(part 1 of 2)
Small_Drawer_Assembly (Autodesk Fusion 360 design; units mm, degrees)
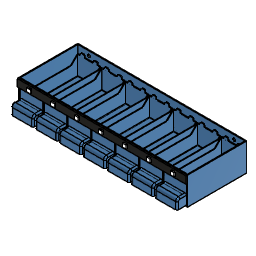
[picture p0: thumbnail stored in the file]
sketch "Sketch1" plane through (0, 0, 0) normal (0, 0, 1) x axis (1, 0, 0)
  line L1 (232.6, 0) -> (0, 0)
  line L2 (232.6, 81.6) -> (232.6, 0)
  line L3 (0, 81.6) -> (232.6, 81.6)
  line L4 (0, 0) -> (0, 81.6)
  line L5 (231.4, 80.4) -> (1.2, 80.4)
  line L6 (231.4, 1.2) -> (231.4, 80.4)
  line L7 (1.2, 1.2) -> (231.4, 1.2)
  line L8 (1.2, 80.4) -> (1.2, 1.2)
  line L9 (31.4, 78.4) -> (3.2, 78.4)
  line L10 (31.4, 3.2) -> (31.4, 78.4)
  line L11 (3.2, 3.2) -> (31.4, 3.2)
  line L12 (3.2, 78.4) -> (3.2, 3.2)
  line L13 (34.2, 80.4) -> (33.4, 80.4)
  line L14 (34.2, 1.2) -> (34.2, 80.4)
  line L15 (33.4, 1.2) -> (34.2, 1.2)
  line L16 (33.4, 80.4) -> (33.4, 1.2)
  line L17 (64.4, 78.4) -> (36.2, 78.4)
  line L18 (36.2, 78.4) -> (36.2, 3.2)
  line L19 (64.4, 3.2) -> (64.4, 78.4)
  line L20 (36.2, 3.2) -> (64.4, 3.2)
  line L21 (97.4, 78.4) -> (69.2, 78.4)
  line L22 (69.2, 78.4) -> (69.2, 3.2)
  line L23 (97.4, 3.2) -> (97.4, 78.4)
  line L24 (69.2, 3.2) -> (97.4, 3.2)
  line L25 (130.4, 78.4) -> (102.2, 78.4)
  line L26 (102.2, 78.4) -> (102.2, 3.2)
  line L27 (130.4, 3.2) -> (130.4, 78.4)
  line L28 (102.2, 3.2) -> (130.4, 3.2)
  line L29 (163.4, 78.4) -> (135.2, 78.4)
  line L30 (135.2, 78.4) -> (135.2, 3.2)
  line L31 (163.4, 3.2) -> (163.4, 78.4)
  line L32 (135.2, 3.2) -> (163.4, 3.2)
  line L33 (196.4, 78.4) -> (168.2, 78.4)
  line L34 (168.2, 78.4) -> (168.2, 3.2)
  line L35 (196.4, 3.2) -> (196.4, 78.4)
  line L36 (168.2, 3.2) -> (196.4, 3.2)
  line L37 (67.2, 80.4) -> (66.4, 80.4)
  line L38 (67.2, 1.2) -> (67.2, 80.4)
  line L39 (66.4, 1.2) -> (67.2, 1.2)
  line L40 (66.4, 80.4) -> (66.4, 1.2)
  line L41 (100.2, 80.4) -> (99.4, 80.4)
  line L42 (100.2, 1.2032) -> (100.2, 80.4)
  line L43 (99.4, 1.2032) -> (100.2, 1.2032)
  line L44 (99.4, 80.4) -> (99.4, 1.2032)
  line L45 (133.2, 80.4) -> (132.4, 80.4)
  line L46 (133.2, 1.2) -> (133.2, 80.4)
  line L47 (132.4, 1.2) -> (133.2, 1.2)
  line L48 (132.4, 80.4) -> (132.4, 1.2)
  line L49 (166.2, 80.4) -> (165.4, 80.4)
  line L50 (166.2, 1.2) -> (166.2, 80.4)
  line L51 (165.4, 1.2) -> (166.2, 1.2)
  line L52 (165.4, 80.4) -> (165.4, 1.2)
  line L53 (199.2, 80.4) -> (198.4, 80.4)
  line L54 (199.2, 1.2) -> (199.2, 80.4)
  line L55 (198.4, 1.2) -> (199.2, 1.2)
  line L56 (198.4, 80.4) -> (198.4, 1.2)
  line L57 (229.4, 78.4) -> (201.2, 78.4)
  line L58 (201.2, 78.4) -> (201.2, 3.2)
  line L59 (201.2, 3.2) -> (229.4, 3.2)
  line L60 (229.4, 3.2) -> (229.4, 78.4)
  line L61 (232.2, 80.4) -> (231.4, 80.4)
  line L62 (231.4, 1.2) -> (232.2, 1.2)
  point P1 (0, 0)
  point P2 (0, 0)
  point P16 (34.2, 1.2)
  point P14 (33.4, 80.4)
  point P38 (66.4, 80.4)
  point P42 (99.4, 80.4)
  point P46 (132.4, 80.4)
  point P50 (165.4, 80.4)
  point P54 (198.4, 80.4)
  point P62 (231.4, 80.4)
  point P5 (0, 81.6)
  point P17 (33.4, 1.2)
  point P39 (67.2, 80.4)
  point P43 (100.2, 80.4)
  point P47 (133.2, 80.4)
  point P51 (166.2, 80.4)
  point P55 (199.2, 80.4)
  horizontal L1
  vertical L2
  horizontal L3
  vertical L4
  coincident P1 P2
  horizontal L5
  vertical L6
  horizontal L7
  vertical L8
  horizontal L9
  vertical L10
  horizontal L11
  vertical L12
  horizontal L13
  vertical L14
  horizontal L15
  vertical L16
  coincident L7 P16
  coincident L5 P14
  horizontal L17
  vertical L19
  horizontal L20
  vertical L18
  horizontal L21
  vertical L23
  horizontal L24
  vertical L22
  horizontal L25
  vertical L27
  horizontal L28
  vertical L26
  horizontal L29
  vertical L31
  horizontal L32
  vertical L30
  horizontal L33
  vertical L35
  horizontal L36
  vertical L34
  horizontal L37
  vertical L38
  horizontal L39
  vertical L40
  coincident L5 P38
  horizontal L41
  vertical L42
  horizontal L43
  vertical L44
  coincident L5 P42
  horizontal L45
  vertical L46
  horizontal L47
  vertical L48
  coincident L5 P46
  horizontal L49
  vertical L50
  horizontal L51
  vertical L52
  coincident L5 P50
  horizontal L53
  vertical L54
  horizontal L55
  vertical L56
  coincident L5 P54
  horizontal L57
  vertical L60
  horizontal L59
  vertical L58
  horizontal L61
  horizontal L62
  coincident L5 P62
  dimension "d1" distance L4 L8 = 1.2
  dimension "d2" distance L3 L5 = 1.2
  dimension "d3" distance L1 L7 = 1.2
  dimension "d4" distance L2 L6 = 1.2
  dimension "d5" distance L8 L12 = 2
  dimension "d6" distance L7 L11 = 2
  dimension "d7" distance L5 L9 = 2
  dimension "d8" distance P2 P5 = 81.6
  dimension "d9" distance P16 P17 = 0.8
  dimension "d10" distance L10 L16 = 2
  dimension "d11" distance L8 L16 = 32.2
  dimension "d12" distance P38 P39 = 0.8
  dimension "d13" distance P42 P43 = 0.8
  dimension "d14" distance P46 P47 = 0.8
  dimension "d15" distance P50 P51 = 0.8
  dimension "d16" distance L14 L18 = 2
  dimension "d17" distance L11 L20 = 0
  dimension "d19" distance L19 L40 = 2
  dimension "d21" distance L14 L40 = 32.2
  dimension "d22" distance L22 L38 = 2
  dimension "d23" distance L23 L44 = 2
  dimension "d24" distance L38 L44 = 32.2
  dimension "d25" distance L26 L42 = 2
  dimension "d26" distance L27 L48 = 2
  dimension "d27" distance L42 L48 = 32.2
  dimension "d28" distance L30 L46 = 2
  dimension "d29" distance L31 L52 = 2
  dimension "d30" distance L46 L52 = 32.2
  dimension "d31" distance L34 L50 = 2
  dimension "d32" distance P54 P55 = 0.8
  dimension "d33" distance L35 L56 = 2
  dimension "d34" distance L50 L56 = 32.2
  dimension "d35" distance L5 L17 = 2
  dimension "d36" distance L5 L21 = 2
  dimension "d38" distance L5 L25 = 2
  dimension "d39" distance L5 L29 = 2
  dimension "d40" distance L5 L33 = 2
  dimension "d41" distance L54 L58 = 2
  dimension "d43" distance L5 L57 = 2
  dimension "d47" distance L7 L59 = 2
  dimension "d48" distance L7 L36 = 2
  dimension "d49" distance L7 L32 = 2
  dimension "d50" distance L7 L28 = 2
  dimension "d51" distance L7 L24 = 2
  dimension "d52" distance L6 L60 = 2
  dimension "d53" distance L6 L54 = 32.2
  dimension "d54" distance L3 L5 = 1.2
  dimension "d306" OffsetX = 0
  dimension "d307" OffsetY = 0
  dimension "d308" OffsetZ = 0
  dimension "d309" AngleZ = 0
extrude "Extrude2" new body sketch "Sketch1" profile of L1 L2 L3 L4 L5 L6 L7 L8 L13 L15 L37 L39 L41 L45 L47 L49 L51 L53 L55 along normal blind 38.2
extrude "Extrude1" add sketch "Sketch1" profile of L5 L6 L7 L8 L9 L10 L11 L12 L13 L14 L15 L16 L17 L18 L19 L20 L21 L22 L23 L24 L25 L26 L27 L28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 along normal blind 38
extrude "Extrude3" cut sketch "Sketch1" profile of L9 L10 L11 L12 L17 L18 L19 L20 L21 L22 L23 L24 L25 L26 L27 L28 L29 L30 L31 L32 L33 L34 L35 L36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 along normal blind 38
extrude "Extrude4" sketch "Sketch1" profile of L5 L6 L7 L8 L9 L10 L11 L12 L14 L16 L17 L18 L19 L20 L21 L22 L23 L24 L25 L26 L27 L28 L29 L30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 blind -36.8
sketch "Sketch2" plane through (0, 0, 0) normal (0, -1, 0) x axis (1, 0, 0)
  line L1 (232.6, 0) -> (0, 0)
  line L2 (232.6, 38.2) -> (232.6, 0)
  line L3 (0, 38.2) -> (232.6, 38.2)
  line L4 (0, 0) -> (0, 38.2)
  line L5 (33.4, 28.2) -> (1.2, 28.2)
  line L6 (33.4, 1.2) -> (33.4, 28.2)
  line L7 (1.2, 1.2) -> (33.4, 1.2)
  line L8 (1.2, 28.2) -> (1.2, 1.2)
  line L9 (66.4, 28.2) -> (34.2, 28.2)
  line L10 (66.4, 1.2) -> (66.4, 28.2)
  line L11 (34.2, 1.2) -> (66.4, 1.2)
  line L12 (34.2, 28.2) -> (34.2, 1.2)
  line L13 (99.4, 28.2) -> (67.2, 28.2)
  line L14 (99.4, 1.2) -> (99.4, 28.2)
  line L15 (67.2, 1.2) -> (99.4, 1.2)
  line L16 (67.2, 28.2) -> (67.2, 1.2)
  line L17 (132.4, 28.2) -> (100.2, 28.2)
  line L18 (132.4, 1.2) -> (132.4, 28.2)
  line L19 (100.2, 1.2) -> (132.4, 1.2)
  line L20 (100.2, 28.2) -> (100.2, 1.2)
  line L21 (165.4, 28.2) -> (133.2, 28.2)
  line L22 (165.4, 1.2) -> (165.4, 28.2)
  line L23 (133.2, 1.2) -> (165.4, 1.2)
  line L24 (133.2, 28.2) -> (133.2, 1.2)
  line L25 (1.2, 38.2) -> (1.2, 1.2)
  line L26 (198.4, 28.2) -> (166.2, 28.2)
  line L27 (166.2, 28.2) -> (166.2, 1.2)
  line L28 (166.2, 1.2) -> (198.4, 1.2)
  line L29 (198.4, 1.2) -> (198.4, 28.2)
  line L30 (231.4, 28.2) -> (199.2, 28.2)
  line L31 (199.2, 28.2) -> (199.2, 1.2)
  line L32 (199.2, 1.2) -> (231.4, 1.2)
  line L33 (231.4, 1.2) -> (231.4, 28.2)
  point P6 (1.2, 28.2)
  point P7 (33.4, 28.2)
  point P12 (66.4, 1.2)
  point P13 (34.2, 1.2)
  point P16 (99.4, 1.2)
  point P17 (67.2, 1.2)
  point P20 (132.4, 1.2)
  point P21 (100.2, 1.2)
  point P24 (165.4, 1.2)
  point P25 (133.2, 1.2)
  point P28 (166.2, 1.2)
  point P30 (198.4, 1.2)
  point P32 (199.2, 1.2)
  point P34 (231.4, 1.2)
  point P9 (1.2, 1.2)
  point P10 (34.2, 28.2)
  point P14 (67.2, 28.2)
  point P33 (231.4, 28.2)
  point P29 (198.4, 28.2)
  point P23 (165.4, 28.2)
  point P19 (132.4, 28.2)
  horizontal L5
  vertical L6
  horizontal L7
  vertical L8
  horizontal L9
  vertical L10
  horizontal L11
  vertical L12
  horizontal L13
  vertical L14
  horizontal L15
  vertical L16
  horizontal L17
  vertical L18
  horizontal L19
  vertical L20
  horizontal L21
  vertical L22
  horizontal L23
  vertical L24
  collinear L8 L25
  horizontal L26
  vertical L29
  horizontal L28
  vertical L27
  horizontal L30
  vertical L33
  horizontal L32
  vertical L31
  dimension "d65" distance P6 P7 = 32.2
  dimension "d66" distance L6 L12 = 0.8
  dimension "d67" distance P12 P13 = 32.2
  dimension "d68" distance L10 L16 = 0.8
  dimension "d69" distance P16 P17 = 32.2
  dimension "d70" distance L14 L20 = 0.8
  dimension "d71" distance P20 P21 = 32.2
  dimension "d72" distance L18 L24 = 0.8
  dimension "d73" distance P24 P25 = 32.2
  dimension "d74" distance P28 P30 = 32.2
  dimension "d75" distance P32 P34 = 32.2
  dimension "d77" distance L22 L27 = 0.8
  dimension "d78" distance L29 L31 = 0.8
  dimension "d79" distance L2 L33 = 1.2
  dimension "d80" distance P6 P9 = 27
  dimension "d81" distance P10 P13 = 27
  dimension "d82" distance P14 P17 = 27
  dimension "d83" distance L3 L5 = 10
  dimension "d84" distance L3 L9 = 10
  dimension "d85" distance L3 L13 = 10
  dimension "d86" distance L3 L17 = 10
  dimension "d87" distance L3 L21 = 10
  dimension "d88" distance L3 L26 = 10
  dimension "d89" distance L3 L30 = 10
  dimension "d90" = 9.8
  dimension "d91" distance P33 P34 = 27
  dimension "d92" distance P29 P30 = 27
  dimension "d93" distance P23 P24 = 27
  dimension "d94" distance P19 P20 = 27
extrude "Extrude5" cut sketch "Sketch2" profile of L5 L6 L7 L8 L9 L10 L11 L12 L13 L14 L15 L16 L17 L18 L19 L20 L21 L22 L23 L24 L25 L26 L27 L28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 against normal blind 1.2
sketch "Sketch3" plane through (0, 80.4, 0) normal (0, -1, 0) x axis (1, 0, 0)
  line L1 (231.4, 38.2) -> (231.4, 1.2)
  line L2 (1.2, 38.2) -> (231.4, 38.2)
  line L3 (1.2, 1.2) -> (1.2, 38.2)
  line L4 (7.1045, 3.2) -> (3.2, 6.3232)
  line L5 (27.8654, 3.2) -> (7.1045, 3.2)
  line L6 (31.4, 6.7364) -> (27.8654, 3.2)
  line L7 (31.4, 6.7364) -> (31.4, 22.6654)
  line L8 (27.8636, 26.2) -> (31.4, 22.6654)
  line L9 (27.8636, 26.2) -> (6.7346, 26.2)
  line L10 (3.2, 22.6636) -> (6.7346, 26.2)
  line L11 (3.2, 6.3232) -> (3.2, 22.6636)
  line L12 (33.4, 28.2) -> (1.2, 28.2)
  line L13 (33.4, 1.2) -> (33.4, 28.2)
  line L14 (1.2, 1.2) -> (33.4, 1.2)
  line L15 (60.8766, 26.2) -> (39.7352, 26.2)
  line L16 (36.2, 6.3232) -> (36.2, 22.6641)
  line L17 (36.2, 22.6641) -> (39.7352, 26.2)
  line L18 (40.1046, 3.2) -> (36.2, 6.3232)
  line L19 (60.8772, 3.2) -> (40.1046, 3.2)
  line L20 (64.4124, 6.7359) -> (60.8772, 3.2)
  line L21 (64.4124, 6.7359) -> (64.4124, 22.6648)
  line L22 (60.8766, 26.2) -> (64.4124, 22.6648)
  line L23 (93.8636, 26.2) -> (72.7347, 26.2)
  line L24 (69.2, 6.3232) -> (69.2, 22.6636)
  line L25 (69.2, 22.6636) -> (72.7347, 26.2)
  line L26 (73.1046, 3.2) -> (69.2, 6.3232)
  line L27 (93.8653, 3.2) -> (73.1046, 3.2)
  line L28 (97.4, 6.7364) -> (93.8653, 3.2)
  line L29 (97.4, 6.7364) -> (97.4, 22.6653)
  line L30 (93.8636, 26.2) -> (97.4, 22.6653)
  line L31 (126.8636, 26.2) -> (105.7347, 26.2)
  line L32 (102.2, 6.3232) -> (102.2, 22.6636)
  line L33 (102.2, 22.6636) -> (105.7347, 26.2)
  line L34 (106.1046, 3.2) -> (102.2, 6.3232)
  line L35 (126.8653, 3.2) -> (106.1046, 3.2)
  line L36 (130.4, 6.7364) -> (126.8653, 3.2)
  line L37 (130.4, 6.7364) -> (130.4, 22.6653)
  line L38 (126.8636, 26.2) -> (130.4, 22.6653)
  line L39 (159.8636, 26.2) -> (138.7347, 26.2)
  line L40 (135.2, 6.3232) -> (135.2, 22.6636)
  line L41 (135.2, 22.6636) -> (138.7347, 26.2)
  line L42 (139.1046, 3.2) -> (135.2, 6.3232)
  line L43 (159.8653, 3.2) -> (139.1046, 3.2)
  line L44 (163.4, 6.7364) -> (159.8653, 3.2)
  line L45 (163.4, 6.7364) -> (163.4, 22.6653)
  line L46 (159.8636, 26.2) -> (163.4, 22.6653)
  line L47 (225.8636, 26.2) -> (204.7347, 26.2)
  line L48 (201.2, 6.3232) -> (201.2, 22.6636)
  line L49 (201.2, 22.6636) -> (204.7347, 26.2)
  line L50 (205.1046, 3.2) -> (201.2, 6.3232)
  line L51 (225.8653, 3.2) -> (205.1046, 3.2)
  line L52 (229.4, 6.7364) -> (225.8653, 3.2)
  line L53 (229.4, 6.7364) -> (229.4, 22.6653)
  line L54 (225.8636, 26.2) -> (229.4, 22.6653)
  line L55 (199.2, 28.2) -> (199.2, 1.2)
  line L56 (231.4, 28.2) -> (199.2, 28.2)
  line L57 (199.2, 1.2) -> (231.4, 1.2)
  line L58 (198.4, 1.2) -> (198.4, 28.2)
  line L59 (165.4, 28.2) -> (133.2, 28.2)
  line L60 (165.4, 1.2) -> (165.4, 28.2)
  line L61 (133.2, 1.2) -> (165.4, 1.2)
  line L62 (133.2, 28.2) -> (133.2, 1.2)
  line L63 (132.4, 1.2) -> (132.4, 28.2)
  line L64 (100.2, 1.2) -> (132.4, 1.2)
  line L65 (132.4, 28.2) -> (100.2, 28.2)
  line L66 (100.2, 28.2) -> (100.2, 1.2)
  line L67 (99.4, 28.2) -> (67.2, 28.2)
  line L68 (99.4, 1.2) -> (99.4, 28.2)
  line L69 (67.2, 1.2) -> (99.4, 1.2)
  line L70 (67.2, 28.2) -> (67.2, 1.2)
  line L71 (66.4, 28.2) -> (34.2, 28.2)
  line L72 (34.2, 28.2) -> (34.2, 1.2)
  line L73 (34.2, 1.2) -> (66.4, 1.2)
  line L74 (192.8636, 26.2) -> (171.7347, 26.2)
  line L75 (168.2, 6.3232) -> (168.2, 22.6636)
  line L76 (168.2, 22.6636) -> (171.7347, 26.2)
  line L77 (172.1046, 3.2) -> (168.2, 6.3232)
  line L78 (192.8653, 3.2) -> (172.1046, 3.2)
  line L79 (196.4, 6.7364) -> (192.8653, 3.2)
  line L80 (196.4, 6.7364) -> (196.4, 22.6653)
  line L81 (192.8636, 26.2) -> (196.4, 22.6653)
  line L82 (166.2, 28.2) -> (166.2, 1.2)
  line L83 (166.2, 1.2) -> (198.4, 1.2)
  line L84 (198.4, 28.2) -> (166.2, 28.2)
  line L85 (34.2, 38) -> (33.4, 38)
  line L86 (34.2, 1.2) -> (34.2, 38)
  line L87 (66.4, 1.2) -> (34.2, 1.2)
  line L88 (66.4, 38) -> (66.4, 1.2)
  line L89 (67.2, 38) -> (66.4, 38)
  line L90 (67.2, 1.2) -> (67.2, 38)
  line L91 (99.4, 1.2) -> (67.2, 1.2)
  line L92 (99.4, 38) -> (99.4, 1.2)
  line L93 (100.2, 38) -> (99.4, 38)
  line L94 (100.2, 1.2) -> (100.2, 38)
  line L95 (132.4, 1.2) -> (100.2, 1.2)
  line L96 (132.4, 38) -> (132.4, 1.2)
  line L97 (133.2, 38) -> (132.4, 38)
  line L98 (133.2, 1.2) -> (133.2, 38)
  line L99 (165.4, 1.2) -> (133.2, 1.2)
  line L100 (165.4, 38) -> (165.4, 1.2)
  line L101 (166.2, 38) -> (165.4, 38)
  line L102 (166.2, 1.2) -> (166.2, 38)
  line L103 (198.4, 1.2) -> (166.2, 1.2)
  line L104 (198.4, 38) -> (198.4, 1.2)
  line L105 (199.2, 38) -> (198.4, 38)
  line L106 (199.2, 1.2) -> (199.2, 38)
  line L107 (231.4, 1.2) -> (199.2, 1.2)
  line L108 (33.4, 1.2) -> (1.2, 1.2)
  line L109 (33.4, 38) -> (33.4, 1.2)
  point P12 (6.7346, 26.2)
  point P13 (3.2, 22.6636)
  point P10 (31.4, 22.6654)
  point P11 (27.8636, 26.2)
  point P6 (3.2, 6.3232)
  point P7 (7.1045, 3.2)
  point P8 (27.8654, 3.2)
  point P9 (31.4, 6.7364)
  point P18 (36.2, 22.6641)
  point P24 (39.7352, 26.2)
  point P20 (64.4124, 22.6648)
  point P22 (60.8766, 26.2)
  point P23 (36.2, 6.3232)
  point P25 (40.1046, 3.2)
  point P19 (64.4124, 6.7359)
  point P21 (60.8772, 3.2)
  point P26 (69.2, 22.6636)
  point P32 (72.7347, 26.2)
  point P28 (97.4, 22.6653)
  point P30 (93.8636, 26.2)
  point P31 (69.2, 6.3232)
  point P33 (73.1046, 3.2)
  point P27 (97.4, 6.7364)
  point P29 (93.8653, 3.2)
  point P34 (102.2, 22.6636)
  point P40 (105.7347, 26.2)
  point P36 (130.4, 22.6653)
  point P38 (126.8636, 26.2)
  point P39 (102.2, 6.3232)
  point P41 (106.1046, 3.2)
  point P35 (130.4, 6.7364)
  point P37 (126.8653, 3.2)
  point P42 (135.2, 22.6636)
  point P48 (138.7347, 26.2)
  point P44 (163.4, 22.6653)
  point P46 (159.8636, 26.2)
  point P47 (135.2, 6.3232)
  point P49 (139.1046, 3.2)
  point P43 (163.4, 6.7364)
  point P45 (159.8653, 3.2)
  point P50 (201.2, 22.6636)
  point P56 (204.7347, 26.2)
  point P52 (229.4, 22.6653)
  point P54 (225.8636, 26.2)
  point P55 (201.2, 6.3232)
  point P57 (205.1046, 3.2)
  point P51 (229.4, 6.7364)
  point P53 (225.8653, 3.2)
  point P80 (168.2, 22.6636)
  point P86 (171.7347, 26.2)
  point P82 (196.4, 22.6653)
  point P84 (192.8636, 26.2)
  point P85 (168.2, 6.3232)
  point P87 (172.1046, 3.2)
  point P81 (196.4, 6.7364)
  point P83 (192.8653, 3.2)
  perpendicular L5 L7
  perpendicular L6 L8
  perpendicular L7 L9
  perpendicular L8 L10
  parallel L3 L11
  perpendicular L19 L21
  perpendicular L20 L22
  perpendicular L15 L21
  perpendicular L17 L22
  perpendicular L27 L29
  perpendicular L28 L30
  perpendicular L23 L29
  perpendicular L25 L30
  perpendicular L35 L37
  perpendicular L36 L38
  perpendicular L31 L37
  perpendicular L33 L38
  perpendicular L43 L45
  perpendicular L44 L46
  perpendicular L39 L45
  perpendicular L41 L46
  perpendicular L51 L53
  perpendicular L52 L54
  perpendicular L47 L53
  perpendicular L49 L54
  perpendicular L78 L80
  perpendicular L79 L81
  perpendicular L74 L80
  perpendicular L76 L81
  dimension "d97" distance P12 P13 = 5
  dimension "d98" distance P10 P11 = 5
  dimension "d99" distance P6 P7 = 5
  dimension "d100" distance P8 P9 = 5
  dimension "d101" distance L9 L12 = 2
  dimension "d102" distance L3 L11 = 2
  dimension "d103" distance L7 L13 = 2
  dimension "d105" distance L5 L14 = 2
  dimension "d106" distance P18 P24 = 5
  dimension "d107" distance P20 P22 = 5
  dimension "d108" distance P23 P25 = 5
  dimension "d109" distance P19 P21 = 5
  dimension "d110" distance P26 P32 = 5
  dimension "d111" distance P28 P30 = 5
  dimension "d112" distance P31 P33 = 5
  dimension "d113" distance P27 P29 = 5
  dimension "d114" distance P34 P40 = 5
  dimension "d115" distance P36 P38 = 5
  dimension "d116" distance P39 P41 = 5
  dimension "d117" distance P35 P37 = 5
  dimension "d118" distance P42 P48 = 5
  dimension "d119" distance P44 P46 = 5
  dimension "d120" distance P47 P49 = 5
  dimension "d121" distance P43 P45 = 5
  dimension "d126" distance P50 P56 = 5
  dimension "d127" distance P52 P54 = 5
  dimension "d128" distance P55 P57 = 5
  dimension "d129" distance P51 P53 = 5
  dimension "d130" distance L48 L55 = 2
  dimension "d131" distance L1 L53 = 2
  dimension "d132" distance L47 L56 = 2
  dimension "d133" distance L51 L57 = 2
  dimension "d135" distance L39 L59 = 2
  dimension "d136" distance L45 L60 = 2
  dimension "d137" distance L43 L61 = 2
  dimension "d138" distance L40 L62 = 2
  dimension "d139" distance L37 L63 = 2
  dimension "d140" distance L35 L64 = 2
  dimension "d141" distance L31 L65 = 2
  dimension "d142" distance L32 L66 = 2
  dimension "d143" distance L23 L67 = 2
  dimension "d145" distance L29 L68 = 2
  dimension "d146" distance L27 L69 = 2
  dimension "d147" distance L24 L70 = 2
  dimension "d148" distance L15 L71 = 2
  dimension "d149" distance L16 L72 = 2
  dimension "d150" distance L19 L73 = 2
  dimension "d151" distance P80 P86 = 5
  dimension "d152" distance P82 P84 = 5
  dimension "d153" distance P85 P87 = 5
  dimension "d154" distance P81 P83 = 5
  dimension "d155" distance L75 L82 = 2
  dimension "d156" distance L58 L80 = 2
  dimension "d157" distance L78 L83 = 2
  dimension "d158" distance L74 L84 = 2
extrude "Extrude6" cut sketch "Sketch3" profile of L4 L5 L6 L7 L8 L9 L10 L11 L15 L16 L17 L18 L19 L20 L21 L22 L23 L24 L25 L26 L27 L28 L29 L30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 against normal blind 1.2
sketch "Sketch4" plane through (33.4, 0, 0) normal (-1, 0, 0) x axis (0, -1, 0)
  line L1 (-80.4, 38) -> (-1.2, 38)
  line L2 (-13.2, 26) -> (-1.2, 38)
  line L3 (16.4477, 38) -> (-1.2, 38)
  line L4 (-80.4, 26) -> (-13.2, 26)
  line L5 (-80.4, 38) -> (-80.4, 26)
  line L6 (-1.2, 38) -> (-80.4, 38)
  line L7 (-80.4, 1.2) -> (-80.4, 38)
  line L8 (0, 1.2) -> (-80.4, 1.2)
  line L9 (0, 28.2) -> (0, 1.2)
  line L10 (-1.2, 28.2) -> (0, 28.2)
  line L11 (-1.2, 38) -> (-1.2, 28.2)
  point P2 (-1.2, 38)
  point P5 (-1.2, 38)
  point P3 (-80.4, 38)
  point P9 (-80.4, 38)
  horizontal L3
  coincident P2 P5
  coincident P3 P9
  dimension "d161" angle L2 L3 = 135
  dimension "d162" distance L4 L6 = 12
extrude "Extrude7" cut sketch "Sketch4" profile of L1 L2 L4 L5 L6 against normal blind 165.8
sketch "Sketch5" plane through (0, 80.4, 0) normal (0, -1, 0) x axis (1, 0, 0)
  line L1 (69.2, 22.6636) -> (69.2, 6.3232)
  line L2 (72.7347, 26.2) -> (69.2, 22.6636)
  line L3 (93.8636, 26.2) -> (72.7347, 26.2)
  line L4 (97.4, 22.6653) -> (93.8636, 26.2)
  line L5 (97.4, 6.7364) -> (97.4, 22.6653)
  line L6 (93.8653, 3.2) -> (97.4, 6.7364)
  line L7 (73.1046, 3.2) -> (93.8653, 3.2)
  line L8 (69.2, 6.3232) -> (73.1046, 3.2)
  line L9 (201.2, 22.6636) -> (201.2, 6.3232)
  line L10 (204.7347, 26.2) -> (201.2, 22.6636)
  line L11 (225.8636, 26.2) -> (204.7347, 26.2)
  line L12 (229.4, 22.6653) -> (225.8636, 26.2)
  line L13 (229.4, 6.7364) -> (229.4, 22.6653)
  line L14 (225.8653, 3.2) -> (229.4, 6.7364)
  line L15 (205.1046, 3.2) -> (225.8653, 3.2)
  line L16 (201.2, 6.3232) -> (205.1046, 3.2)
  line L17 (102.2, 22.6636) -> (102.2, 6.3232)
  line L18 (105.7347, 26.2) -> (102.2, 22.6636)
  line L19 (126.8636, 26.2) -> (105.7347, 26.2)
  line L20 (130.4, 22.6653) -> (126.8636, 26.2)
  line L21 (130.4, 6.7364) -> (130.4, 22.6653)
  line L22 (126.8653, 3.2) -> (130.4, 6.7364)
  line L23 (106.1046, 3.2) -> (126.8653, 3.2)
  line L24 (102.2, 6.3232) -> (106.1046, 3.2)
  line L25 (36.2, 22.6641) -> (36.2, 6.3232)
  line L26 (39.7352, 26.2) -> (36.2, 22.6641)
  line L27 (60.8766, 26.2) -> (39.7352, 26.2)
  line L28 (64.4124, 22.6648) -> (60.8766, 26.2)
  line L29 (64.4124, 6.7359) -> (64.4124, 22.6648)
  line L30 (60.8772, 3.2) -> (64.4124, 6.7359)
  line L31 (40.1046, 3.2) -> (60.8772, 3.2)
  line L32 (36.2, 6.3232) -> (40.1046, 3.2)
  line L33 (168.2, 22.6636) -> (168.2, 6.3232)
  line L34 (171.7347, 26.2) -> (168.2, 22.6636)
  line L35 (192.8636, 26.2) -> (171.7347, 26.2)
  line L36 (196.4, 22.6653) -> (192.8636, 26.2)
  line L37 (196.4, 6.7364) -> (196.4, 22.6653)
  line L38 (192.8653, 3.2) -> (196.4, 6.7364)
  line L39 (172.1046, 3.2) -> (192.8653, 3.2)
  line L40 (168.2, 6.3232) -> (172.1046, 3.2)
  line L41 (135.2, 22.6636) -> (135.2, 6.3232)
  line L42 (138.7347, 26.2) -> (135.2, 22.6636)
  line L43 (159.8636, 26.2) -> (138.7347, 26.2)
  line L44 (163.4, 22.6653) -> (159.8636, 26.2)
  line L45 (163.4, 6.7364) -> (163.4, 22.6653)
  line L46 (159.8653, 3.2) -> (163.4, 6.7364)
  line L47 (139.1046, 3.2) -> (159.8653, 3.2)
  line L48 (135.2, 6.3232) -> (139.1046, 3.2)
  line L49 (3.2, 22.6636) -> (3.2, 6.3232)
  line L50 (6.7346, 26.2) -> (3.2, 22.6636)
  line L51 (27.8636, 26.2) -> (6.7346, 26.2)
  line L52 (31.4, 22.6654) -> (27.8636, 26.2)
  line L53 (31.4, 6.7364) -> (31.4, 22.6654)
  line L54 (27.8654, 3.2) -> (31.4, 6.7364)
  line L55 (7.1045, 3.2) -> (27.8654, 3.2)
  line L56 (3.2, 6.3232) -> (7.1045, 3.2)
  line L57 (231.4, 38.2) -> (231.4, 1.2)
  line L58 (1.2, 38.2) -> (231.4, 38.2)
  line L59 (1.2, 1.2) -> (1.2, 38.2)
  line L60 (199.2, 1.2) -> (199.2, 26)
  line L61 (231.4, 1.2) -> (199.2, 1.2)
  line L62 (33.4, 1.2) -> (1.2, 1.2)
  line L63 (33.4, 26) -> (33.4, 1.2)
  line L64 (34.2, 26) -> (33.4, 26)
  line L65 (34.2, 1.2) -> (34.2, 26)
  line L66 (66.4, 1.2) -> (34.2, 1.2)
  line L67 (66.4, 26) -> (66.4, 1.2)
  line L68 (67.2, 26) -> (66.4, 26)
  line L69 (67.2, 1.2) -> (67.2, 26)
  line L70 (99.4, 1.2) -> (67.2, 1.2)
  line L71 (99.4, 26) -> (99.4, 1.2)
  line L72 (100.2, 26) -> (99.4, 26)
  line L73 (100.2, 1.2) -> (100.2, 26)
  line L74 (132.4, 1.2) -> (100.2, 1.2)
  line L75 (132.4, 26) -> (132.4, 1.2)
  line L76 (133.2, 26) -> (132.4, 26)
  line L77 (133.2, 1.2) -> (133.2, 26)
  line L78 (165.4, 1.2) -> (133.2, 1.2)
  line L79 (165.4, 26) -> (165.4, 1.2)
  line L80 (166.2, 26) -> (165.4, 26)
  line L81 (166.2, 1.2) -> (166.2, 26)
  line L82 (198.4, 1.2) -> (166.2, 1.2)
  line L83 (198.4, 26) -> (198.4, 1.2)
  line L84 (199.2, 26) -> (198.4, 26)
  circle C1 centre (216.3, 32.2) radius 2
  circle C2 centre (16.3, 32.2) radius 2
  point P63 (16.3, 32.2)
  point P62 (216.3, 32.2)
  dimension "d165" diameter C1 = 4
  dimension "d166" diameter C2 = 4
  dimension "d167" distance L59 P63 = 15.1
  dimension "d168" distance L58 P63 = 6
  dimension "d169" distance L57 P62 = 15.1
  dimension "d170" distance L58 P62 = 6
extrude "Extrude8" cut sketch "Sketch5" profile of C1 C2 against normal blind 1.2
sketch "Sketch1" plane through (0, 0, 0) normal (0, 0, 1) x axis (1, 0, 0)
  line L1 (31.8, 0) -> (0, 0)
  line L2 (31.8, 80) -> (31.8, 0)
  line L3 (0, 80) -> (31.8, 80)
  line L4 (0, 0) -> (0, 80)
  point P1 (0, 0)
  point P2 (0, 0)
  point P3 (31.8, 0)
  point P4 (31.8, 80)
  horizontal L1
  vertical L2
  horizontal L3
  vertical L4
  coincident P1 P2
  dimension "d1_1" distance P2 P3 = 31.8
  dimension "d2_1" distance P3 P4 = 80
extrude "Extrude1" new body sketch "Sketch1" along normal blind 26.2 named "d3_1"
shell "Shell1" innerThickness 0.8 named "d5_1"
work_plane "WorkPlane1" AlongDistance -18.4 named "d6_1"
sketch "Sketch3" plane through (0, 80, 0) normal (0, 1, 0) x axis (-1, 0, 0)
  line L1 (0, 0) -> (-31.8, 0)
  line L2 (0, 26.2) -> (0, 0)
  line L3 (-31.8, 26.2) -> (0, 26.2)
  line L4 (-31.8, 0) -> (-31.8, 26.2)
  line L5 (-15.9, 0) -> (-15.9, 26.2)
  line L6 (-27.55, 28.45) -> (-27.55, 27.45)
  line L7 (-23.3, 29.7) -> (-26.3, 29.7)
  line L8 (-22.05, 27.45) -> (-22.05, 28.45)
  line L9 (-20.8, 26.2) -> (-28.8, 26.2)
  line L10 (-8.5, 29.7) -> (-5.5, 29.7)
  line L11 (-4.25, 28.45) -> (-4.25, 27.45)
  line L12 (-11, 26.2) -> (-3, 26.2)
  line L13 (-9.75, 27.45) -> (-9.75, 28.45)
  arc A1 centre (-28.8, 27.45) radius 1.25 clockwise from (-27.55, 27.45) to (-28.8, 26.2)
  arc A2 centre (-26.3, 28.45) radius 1.25 clockwise from (-27.55, 28.45) to (-26.3, 29.7)
  arc A3 centre (-23.3, 28.45) radius 1.25 clockwise from (-23.3, 29.7) to (-22.05, 28.45)
  arc A4 centre (-20.8, 27.45) radius 1.25 clockwise from (-20.8, 26.2) to (-22.05, 27.45)
  arc A5 centre (-5.5, 28.45) radius 1.25 clockwise from (-5.5, 29.7) to (-4.25, 28.45)
  arc A6 centre (-11, 27.45) radius 1.25 clockwise from (-9.75, 27.45) to (-11, 26.2)
  arc A7 centre (-3, 27.45) radius 1.25 clockwise from (-3, 26.2) to (-4.25, 27.45)
  arc A8 centre (-8.5, 28.45) radius 1.25 clockwise from (-9.75, 28.45) to (-8.5, 29.7)
  point P10 (-15.9, 26.2)
  point P11 (-15.9, 0)
  point P20 (-24.8, 29.7)
  point P12 (-27.55, 27.45)
  point P27 (-4.25, 27.45)
  point P13 (-27.55, 28.45)
  point P21 (-4.25, 28.45)
  point P14 (-26.3, 29.7)
  point P28 (-5.5, 29.7)
  point P15 (-23.3, 29.7)
  point P26 (-8.5, 29.7)
  point P16 (-22.05, 28.45)
  point P23 (-9.75, 28.45)
  point P17 (-22.05, 27.45)
  point P22 (-9.75, 27.45)
  point P18 (-28.8, 26.2)
  point P30 (-3, 26.2)
  point P19 (-20.8, 26.2)
  point P29 (-11, 26.2)
  point P31 (-7, 29.7)
  midpoint L3 P10
  perpendicular L3 L5
  coincident L1 P11
  horizontal L7
  tangent L7 A2
  tangent L6 A2
  tangent L6 A1
  tangent L7 A3
  tangent L8 A3
  tangent L8 A4
  tangent L9 A4
  tangent L9 A1
  equal A1 A2
  equal A2 A3
  equal A3 A4
  collinear L3 L9
  vertical L8
  vertical L6
  midpoint L7 P20
  symmetric L5 P12 P27
  symmetric L5 P13 P21
  symmetric L5 P14 P28
  symmetric L5 P15 P26
  symmetric L5 P16 P23
  symmetric L5 P17 P22
  symmetric L5 P18 P30
  symmetric L5 P19 P29
  symmetric L5 P20 P31
  symmetric L5 A1 A7
  symmetric L5 A2 A5
  symmetric L5 A3 A8
  symmetric L5 A4 A6
  dimension "d18" distance L4 P20 = 7
  dimension "d19_1" distance L7 L9 = 3.5
  dimension "d20" distance L6 L8 = 5.5
  dimension "d21_1" radius A1 = 1.25
extrude "Extrude3" add sketch "Sketch3" profile of L3 A1 A2 A3 A4 L6 L7 L8 L9 A5 L10 A6 A7 L11 L12 A8 L13 against normal blind 0.8 named "d22_1"
sketch "Sketch4" plane through (31.8, 0, 0) normal (1, 0, 0) x axis (0, 1, 0)
  line L1 (80, 0) -> (0, 0)
  line L2 (80, 26.2) -> (80, 0)
  line L3 (0, 26.2) -> (80, 26.2)
  line L4 (0, 0) -> (0, 26.2)
  line L5 (10.1071, 17) -> (0.9071, 26.2)
  line L6 (7.8528, 26.2) -> (0.9071, 26.2)
  line L7 (69.7311, 17) -> (10.1071, 17)
  line L8 (78.9311, 26.2) -> (69.7311, 17)
  line L9 (0.9071, 26.2) -> (78.9311, 26.2)
  point P6 (0.9071, 26.2)
  point P10 (78.9311, 26.2)
  horizontal L6
  coincident L3 P6
  horizontal L7
  coincident L3 P10
  dimension "d24_1" angle L5 L6 = 45
  dimension "d25_1" angle L7 L8 = 135
  dimension "d26_1" distance L1 L7 = 17
extrude "Extrude4" cut sketch "Sketch4" profile of L3 L5 L7 L8 L9 against normal blind 31.8 named "d27_1"
extrude "Extrude5" add of existing geometry blind 0.4 named "d29_1"
sketch "Sketch5" plane through (0, 0, 0) normal (0, -1, 0) x axis (1, 0, 0)
  line L1 (31.8, 0) -> (0, 0)
  line L2 (31.8, 26.2) -> (31.8, 0)
  line L3 (0, 26.2) -> (31.8, 26.2)
  line L4 (0, 0) -> (0, 26.2)
  line L5 (31.3, 13.8) -> (0.5, 13.8)
  line L6 (31.3, 13) -> (31.3, 13.8)
  line L7 (0.5, 13) -> (31.3, 13)
  line L8 (0.5, 13.8) -> (0.5, 13)
  horizontal L5
  vertical L6
  horizontal L7
  vertical L8
  dimension "d31_1" distance L4 L8 = 0.5
  dimension "d32_1" distance L2 L6 = 0.5
  dimension "d33_1" distance L5 L7 = 0.8
  dimension "d34_1" distance L1 L7 = 13
extrude "Extrude6" add sketch "Sketch5" profile of L5 L6 L7 L8 along normal blind 13 named "d35_1"
sketch "Sketch6" plane through (0, 0, 13) normal (0, 0, -1) x axis (1, 0, 0)
  line L1 (31.3, 0) -> (0.5, 0)
  line L2 (31.3, 13) -> (31.3, 0)
  line L3 (0.5, 13) -> (31.3, 13)
  line L4 (0.5, 0) -> (0.5, 13)
  line L5 (31.3, 13) -> (0.5, 13)
  line L6 (31.3, 12.2) -> (31.3, 13)
  line L7 (0.5, 12.2) -> (31.3, 12.2)
  line L8 (0.5, 13) -> (0.5, 12.2)
  point P5 (0.5, 13)
  point P6 (0.5, 13)
  point P9 (0.5, 12.2)
  horizontal L5
  vertical L6
  horizontal L7
  vertical L8
  coincident P5 P6
  dimension "d37" distance P6 P9 = 0.8
extrude "Extrude7" add sketch "Sketch6" profile of L2 L3 L4 L5 L6 L7 L8 along normal blind 13 named "d38_1"
sketch "Sketch8" plane through (0, 0, 13) normal (0, 0, -1) x axis (1, 0, 0)
  line L1 (0.5, 12.2) -> (31.3, 12.2)
  line L2 (0.5, 0) -> (0.5, 12.2)
  line L3 (31.3, 0) -> (0.5, 0)
  line L4 (31.3, 12.2) -> (31.3, 0)
  line L5 (0.5, 0) -> (1.3, 0)
  line L6 (0.5, 12.2) -> (0.5, 0)
  line L7 (1.3, 12.2) -> (0.5, 12.2)
  line L8 (1.3, 0) -> (1.3, 12.2)
  line L9 (30.5, 0) -> (31.3, 0)
  line L10 (30.5, 12.2) -> (30.5, 0)
  line L11 (31.3, 12.2) -> (30.5, 12.2)
  line L12 (31.3, 0) -> (31.3, 12.2)
  point P3 (0.5, 12.2)
  point P8 (0.5, 12.2)
  point P6 (1.3, 0)
  point P12 (30.5, 12.2)
  point P5 (31.3, 0)
  point P10 (31.3, 0)
  point P13 (31.3, 12.2)
  point P9 (1.3, 12.2)
  horizontal L5
  vertical L6
  horizontal L7
  vertical L8
  coincident P3 P8
  coincident L3 P6
  horizontal L9
  vertical L10
  horizontal L11
  vertical L12
  coincident L1 P12
  coincident P5 P10
  dimension "d45" distance P12 P13 = 0.8
  dimension "d46" distance P8 P9 = 0.8
extrude "Extrude9" add sketch "Sketch8" along normal blind 13 named "d47_1"
fillet "Fillet2" radius 4 named "d49_1"
chamfer "Chamfer1" distance 3 named "d50_1"
fillet "Fillet3" radius 2 named "d51_1"
fillet "Fillet4" radius 2 named "d52_1"
sketch "Sketch1" plane through (0, 0, 0) normal (0, 0, 1) x axis (1, 0, 0)
  line L1 (31.8, 0) -> (0, 0)
  line L2 (31.8, 80) -> (31.8, 0)
  line L3 (0, 80) -> (31.8, 80)
  line L4 (0, 0) -> (0, 80)
  point P1 (0, 0)
  point P2 (0, 0)
  point P3 (31.8, 0)
  point P4 (31.8, 80)
  horizontal L1
  vertical L2
  horizontal L3
  vertical L4
  coincident P1 P2
  dimension "d1_2" distance P2 P3 = 31.8
  dimension "d2_2" distance P3 P4 = 80
extrude "Extrude1" new body sketch "Sketch1" along normal blind 26.2 named "d3_2"
shell "Shell1" innerThickness 0.8 named "d5_2"
work_plane "WorkPlane1" AlongDistance -18.4 named "d6_2"
sketch "Sketch3" plane through (0, 80, 0) normal (0, 1, 0) x axis (-1, 0, 0)
  line L1 (0, 0) -> (-31.8, 0)
  line L2 (0, 26.2) -> (0, 0)
  line L3 (-31.8, 26.2) -> (0, 26.2)
  line L4 (-31.8, 0) -> (-31.8, 26.2)
  line L5 (-15.9, 0) -> (-15.9, 26.2)
  line L6 (-27.55, 28.45) -> (-27.55, 27.45)
  line L7 (-23.3, 29.7) -> (-26.3, 29.7)
  line L8 (-22.05, 27.45) -> (-22.05, 28.45)
  line L9 (-20.8, 26.2) -> (-28.8, 26.2)
  line L10 (-8.5, 29.7) -> (-5.5, 29.7)
  line L11 (-4.25, 28.45) -> (-4.25, 27.45)
  line L12 (-11, 26.2) -> (-3, 26.2)
  line L13 (-9.75, 27.45) -> (-9.75, 28.45)
  arc A1 centre (-28.8, 27.45) radius 1.25 clockwise from (-27.55, 27.45) to (-28.8, 26.2)
  arc A2 centre (-26.3, 28.45) radius 1.25 clockwise from (-27.55, 28.45) to (-26.3, 29.7)
  arc A3 centre (-23.3, 28.45) radius 1.25 clockwise from (-23.3, 29.7) to (-22.05, 28.45)
  arc A4 centre (-20.8, 27.45) radius 1.25 clockwise from (-20.8, 26.2) to (-22.05, 27.45)
  arc A5 centre (-5.5, 28.45) radius 1.25 clockwise from (-5.5, 29.7) to (-4.25, 28.45)
  arc A6 centre (-11, 27.45) radius 1.25 clockwise from (-9.75, 27.45) to (-11, 26.2)
  arc A7 centre (-3, 27.45) radius 1.25 clockwise from (-3, 26.2) to (-4.25, 27.45)
  arc A8 centre (-8.5, 28.45) radius 1.25 clockwise from (-9.75, 28.45) to (-8.5, 29.7)
  point P10 (-15.9, 26.2)
  point P11 (-15.9, 0)
  point P20 (-24.8, 29.7)
  point P12 (-27.55, 27.45)
  point P27 (-4.25, 27.45)
  point P13 (-27.55, 28.45)
  point P21 (-4.25, 28.45)
  point P14 (-26.3, 29.7)
  point P28 (-5.5, 29.7)
  point P15 (-23.3, 29.7)
  point P26 (-8.5, 29.7)
  point P16 (-22.05, 28.45)
  point P23 (-9.75, 28.45)
  point P17 (-22.05, 27.45)
  point P22 (-9.75, 27.45)
  point P18 (-28.8, 26.2)
  point P30 (-3, 26.2)
  point P19 (-20.8, 26.2)
  point P29 (-11, 26.2)
  point P31 (-7, 29.7)
  midpoint L3 P10
  perpendicular L3 L5
  coincident L1 P11
  horizontal L7
  tangent L7 A2
  tangent L6 A2
  tangent L6 A1
  tangent L7 A3
  tangent L8 A3
  tangent L8 A4
  tangent L9 A4
  tangent L9 A1
  equal A1 A2
  equal A2 A3
  equal A3 A4
  collinear L3 L9
  vertical L8
  vertical L6
  midpoint L7 P20
  symmetric L5 P12 P27
  symmetric L5 P13 P21
  symmetric L5 P14 P28
  symmetric L5 P15 P26
  symmetric L5 P16 P23
  symmetric L5 P17 P22
  symmetric L5 P18 P30
  symmetric L5 P19 P29
  symmetric L5 P20 P31
  symmetric L5 A1 A7
  symmetric L5 A2 A5
  symmetric L5 A3 A8
  symmetric L5 A4 A6
  dimension "d18_1" distance L4 P20 = 7
  dimension "d19_2" distance L7 L9 = 3.5
  dimension "d20_1" distance L6 L8 = 5.5
  dimension "d21_2" radius A1 = 1.25
extrude "Extrude3" add sketch "Sketch3" profile of L3 A1 A2 A3 A4 L6 L7 L8 L9 A5 L10 A6 A7 L11 L12 A8 L13 against normal blind 0.8 named "d22_2"
sketch "Sketch4" plane through (31.8, 0, 0) normal (1, 0, 0) x axis (0, 1, 0)
  line L1 (80, 0) -> (0, 0)
  line L2 (80, 26.2) -> (80, 0)
  line L3 (0, 26.2) -> (80, 26.2)
  line L4 (0, 0) -> (0, 26.2)
  line L5 (10.1071, 17) -> (0.9071, 26.2)
  line L6 (7.8528, 26.2) -> (0.9071, 26.2)
  line L7 (69.7311, 17) -> (10.1071, 17)
  line L8 (78.9311, 26.2) -> (69.7311, 17)
  line L9 (0.9071, 26.2) -> (78.9311, 26.2)
  point P6 (0.9071, 26.2)
  point P10 (78.9311, 26.2)
  horizontal L6
  coincident L3 P6
  horizontal L7
  coincident L3 P10
  dimension "d24_2" angle L5 L6 = 45
  dimension "d25_2" angle L7 L8 = 135
  dimension "d26_2" distance L1 L7 = 17
extrude "Extrude4" cut sketch "Sketch4" profile of L3 L5 L7 L8 L9 against normal blind 31.8 named "d27_2"
extrude "Extrude5" add of existing geometry blind 0.4 named "d29_2"
sketch "Sketch5" plane through (0, 0, 0) normal (0, -1, 0) x axis (1, 0, 0)
  line L1 (31.8, 0) -> (0, 0)
  line L2 (31.8, 26.2) -> (31.8, 0)
  line L3 (0, 26.2) -> (31.8, 26.2)
  line L4 (0, 0) -> (0, 26.2)
  line L5 (31.3, 13.8) -> (0.5, 13.8)
  line L6 (31.3, 13) -> (31.3, 13.8)
  line L7 (0.5, 13) -> (31.3, 13)
  line L8 (0.5, 13.8) -> (0.5, 13)
  horizontal L5
  vertical L6
  horizontal L7
  vertical L8
  dimension "d31_2" distance L4 L8 = 0.5
  dimension "d32_2" distance L2 L6 = 0.5
  dimension "d33_2" distance L5 L7 = 0.8
  dimension "d34_2" distance L1 L7 = 13
extrude "Extrude6" add sketch "Sketch5" profile of L5 L6 L7 L8 along normal blind 13 named "d35_2"
sketch "Sketch6" plane through (0, 0, 13) normal (0, 0, -1) x axis (1, 0, 0)
  line L1 (31.3, 0) -> (0.5, 0)
  line L2 (31.3, 13) -> (31.3, 0)
  line L3 (0.5, 13) -> (31.3, 13)
  line L4 (0.5, 0) -> (0.5, 13)
  line L5 (31.3, 13) -> (0.5, 13)
  line L6 (31.3, 12.2) -> (31.3, 13)
  line L7 (0.5, 12.2) -> (31.3, 12.2)
  line L8 (0.5, 13) -> (0.5, 12.2)
  point P5 (0.5, 13)
  point P6 (0.5, 13)
  point P9 (0.5, 12.2)
  horizontal L5
  vertical L6
  horizontal L7
  vertical L8
  coincident P5 P6
  dimension "d37_1" distance P6 P9 = 0.8
extrude "Extrude7" add sketch "Sketch6" profile of L2 L3 L4 L5 L6 L7 L8 along normal blind 13 named "d38_2"
sketch "Sketch8" plane through (0, 0, 13) normal (0, 0, -1) x axis (1, 0, 0)
  line L1 (0.5, 12.2) -> (31.3, 12.2)
  line L2 (0.5, 0) -> (0.5, 12.2)
  line L3 (31.3, 0) -> (0.5, 0)
  line L4 (31.3, 12.2) -> (31.3, 0)
  line L5 (0.5, 0) -> (1.3, 0)
  line L6 (0.5, 12.2) -> (0.5, 0)
  line L7 (1.3, 12.2) -> (0.5, 12.2)
  line L8 (1.3, 0) -> (1.3, 12.2)
  line L9 (30.5, 0) -> (31.3, 0)
  line L10 (30.5, 12.2) -> (30.5, 0)
  line L11 (31.3, 12.2) -> (30.5, 12.2)
  line L12 (31.3, 0) -> (31.3, 12.2)
  point P3 (0.5, 12.2)
  point P8 (0.5, 12.2)
  point P6 (1.3, 0)
  point P12 (30.5, 12.2)
  point P5 (31.3, 0)
  point P10 (31.3, 0)
  point P13 (31.3, 12.2)
  point P9 (1.3, 12.2)
  horizontal L5
  vertical L6
  horizontal L7
  vertical L8
  coincident P3 P8
  coincident L3 P6
  horizontal L9
  vertical L10
  horizontal L11
  vertical L12
  coincident L1 P12
  coincident P5 P10
  dimension "d45_1" distance P12 P13 = 0.8
  dimension "d46_1" distance P8 P9 = 0.8
extrude "Extrude9" add sketch "Sketch8" along normal blind 13 named "d47_2"
fillet "Fillet2" radius 4 named "d49_2"
chamfer "Chamfer1" distance 3 named "d50_2"
fillet "Fillet3" radius 2 named "d51_2"
fillet "Fillet4" radius 2 named "d52_2"
sketch "Sketch1" plane through (0, 0, 0) normal (0, 0, 1) x axis (1, 0, 0)
  line L1 (31.8, 0) -> (0, 0)
  line L2 (31.8, 80) -> (31.8, 0)
  line L3 (0, 80) -> (31.8, 80)
  line L4 (0, 0) -> (0, 80)
  point P1 (0, 0)
  point P2 (0, 0)
  point P3 (31.8, 0)
  point P4 (31.8, 80)
  horizontal L1
  vertical L2
  horizontal L3
  vertical L4
  coincident P1 P2
  dimension "d1_3" distance P2 P3 = 31.8
  dimension "d2_3" distance P3 P4 = 80
extrude "Extrude1" new body sketch "Sketch1" along normal blind 26.2 named "d3_3"
shell "Shell1" innerThickness 0.8 named "d5_3"
work_plane "WorkPlane1" AlongDistance -18.4 named "d6_3"
sketch "Sketch3" plane through (0, 80, 0) normal (0, 1, 0) x axis (-1, 0, 0)
  line L1 (0, 0) -> (-31.8, 0)
  line L2 (0, 26.2) -> (0, 0)
  line L3 (-31.8, 26.2) -> (0, 26.2)
  line L4 (-31.8, 0) -> (-31.8, 26.2)
  line L5 (-15.9, 0) -> (-15.9, 26.2)
  line L6 (-27.55, 28.45) -> (-27.55, 27.45)
  line L7 (-23.3, 29.7) -> (-26.3, 29.7)
  line L8 (-22.05, 27.45) -> (-22.05, 28.45)
  line L9 (-20.8, 26.2) -> (-28.8, 26.2)
  line L10 (-8.5, 29.7) -> (-5.5, 29.7)
  line L11 (-4.25, 28.45) -> (-4.25, 27.45)
  line L12 (-11, 26.2) -> (-3, 26.2)
  line L13 (-9.75, 27.45) -> (-9.75, 28.45)
  arc A1 centre (-28.8, 27.45) radius 1.25 clockwise from (-27.55, 27.45) to (-28.8, 26.2)
  arc A2 centre (-26.3, 28.45) radius 1.25 clockwise from (-27.55, 28.45) to (-26.3, 29.7)
  arc A3 centre (-23.3, 28.45) radius 1.25 clockwise from (-23.3, 29.7) to (-22.05, 28.45)
  arc A4 centre (-20.8, 27.45) radius 1.25 clockwise from (-20.8, 26.2) to (-22.05, 27.45)
  arc A5 centre (-5.5, 28.45) radius 1.25 clockwise from (-5.5, 29.7) to (-4.25, 28.45)
  arc A6 centre (-11, 27.45) radius 1.25 clockwise from (-9.75, 27.45) to (-11, 26.2)
  arc A7 centre (-3, 27.45) radius 1.25 clockwise from (-3, 26.2) to (-4.25, 27.45)
  arc A8 centre (-8.5, 28.45) radius 1.25 clockwise from (-9.75, 28.45) to (-8.5, 29.7)
  point P10 (-15.9, 26.2)
  point P11 (-15.9, 0)
  point P20 (-24.8, 29.7)
  point P12 (-27.55, 27.45)
  point P27 (-4.25, 27.45)
  point P13 (-27.55, 28.45)
  point P21 (-4.25, 28.45)
  point P14 (-26.3, 29.7)
  point P28 (-5.5, 29.7)
  point P15 (-23.3, 29.7)
  point P26 (-8.5, 29.7)
  point P16 (-22.05, 28.45)
  point P23 (-9.75, 28.45)
  point P17 (-22.05, 27.45)
  point P22 (-9.75, 27.45)
  point P18 (-28.8, 26.2)
  point P30 (-3, 26.2)
  point P19 (-20.8, 26.2)
  point P29 (-11, 26.2)
  point P31 (-7, 29.7)
  midpoint L3 P10
  perpendicular L3 L5
  coincident L1 P11
  horizontal L7
  tangent L7 A2
  tangent L6 A2
  tangent L6 A1
  tangent L7 A3
  tangent L8 A3
  tangent L8 A4
  tangent L9 A4
  tangent L9 A1
  equal A1 A2
  equal A2 A3
  equal A3 A4
  collinear L3 L9
  vertical L8
  vertical L6
  midpoint L7 P20
  symmetric L5 P12 P27
  symmetric L5 P13 P21
  symmetric L5 P14 P28
  symmetric L5 P15 P26
  symmetric L5 P16 P23
  symmetric L5 P17 P22
  symmetric L5 P18 P30
  symmetric L5 P19 P29
  symmetric L5 P20 P31
  symmetric L5 A1 A7
  symmetric L5 A2 A5
  symmetric L5 A3 A8
  symmetric L5 A4 A6
  dimension "d18_2" distance L4 P20 = 7
  dimension "d19_3" distance L7 L9 = 3.5
  dimension "d20_2" distance L6 L8 = 5.5
  dimension "d21_3" radius A1 = 1.25
extrude "Extrude3" add sketch "Sketch3" profile of L3 A1 A2 A3 A4 L6 L7 L8 L9 A5 L10 A6 A7 L11 L12 A8 L13 against normal blind 0.8 named "d22_3"
sketch "Sketch4" plane through (31.8, 0, 0) normal (1, 0, 0) x axis (0, 1, 0)
  line L1 (80, 0) -> (0, 0)
  line L2 (80, 26.2) -> (80, 0)
  line L3 (0, 26.2) -> (80, 26.2)
  line L4 (0, 0) -> (0, 26.2)
  line L5 (10.1071, 17) -> (0.9071, 26.2)
  line L6 (7.8528, 26.2) -> (0.9071, 26.2)
  line L7 (69.7311, 17) -> (10.1071, 17)
  line L8 (78.9311, 26.2) -> (69.7311, 17)
  line L9 (0.9071, 26.2) -> (78.9311, 26.2)
  point P6 (0.9071, 26.2)
  point P10 (78.9311, 26.2)
  horizontal L6
  coincident L3 P6
  horizontal L7
  coincident L3 P10
  dimension "d24_3" angle L5 L6 = 45
  dimension "d25_3" angle L7 L8 = 135
  dimension "d26_3" distance L1 L7 = 17
extrude "Extrude4" cut sketch "Sketch4" profile of L3 L5 L7 L8 L9 against normal blind 31.8 named "d27_3"
extrude "Extrude5" add of existing geometry blind 0.4 named "d29_3"
sketch "Sketch5" plane through (0, 0, 0) normal (0, -1, 0) x axis (1, 0, 0)
  line L1 (31.8, 0) -> (0, 0)
  line L2 (31.8, 26.2) -> (31.8, 0)
  line L3 (0, 26.2) -> (31.8, 26.2)
  line L4 (0, 0) -> (0, 26.2)
  line L5 (31.3, 13.8) -> (0.5, 13.8)
  line L6 (31.3, 13) -> (31.3, 13.8)
  line L7 (0.5, 13) -> (31.3, 13)
  line L8 (0.5, 13.8) -> (0.5, 13)
  horizontal L5
  vertical L6
  horizontal L7
  vertical L8
  dimension "d31_3" distance L4 L8 = 0.5
  dimension "d32_3" distance L2 L6 = 0.5
  dimension "d33_3" distance L5 L7 = 0.8
  dimension "d34_3" distance L1 L7 = 13
extrude "Extrude6" add sketch "Sketch5" profile of L5 L6 L7 L8 along normal blind 13 named "d35_3"
sketch "Sketch6" plane through (0, 0, 13) normal (0, 0, -1) x axis (1, 0, 0)
  line L1 (31.3, 0) -> (0.5, 0)
  line L2 (31.3, 13) -> (31.3, 0)
  line L3 (0.5, 13) -> (31.3, 13)
  line L4 (0.5, 0) -> (0.5, 13)
  line L5 (31.3, 13) -> (0.5, 13)
  line L6 (31.3, 12.2) -> (31.3, 13)
  line L7 (0.5, 12.2) -> (31.3, 12.2)
  line L8 (0.5, 13) -> (0.5, 12.2)
  point P5 (0.5, 13)
  point P6 (0.5, 13)
  point P9 (0.5, 12.2)
  horizontal L5
  vertical L6
  horizontal L7
  vertical L8
  coincident P5 P6
  dimension "d37_2" distance P6 P9 = 0.8
extrude "Extrude7" add sketch "Sketch6" profile of L2 L3 L4 L5 L6 L7 L8 along normal blind 13 named "d38_3"
sketch "Sketch8" plane through (0, 0, 13) normal (0, 0, -1) x axis (1, 0, 0)
  line L1 (0.5, 12.2) -> (31.3, 12.2)
  line L2 (0.5, 0) -> (0.5, 12.2)
  line L3 (31.3, 0) -> (0.5, 0)
  line L4 (31.3, 12.2) -> (31.3, 0)
  line L5 (0.5, 0) -> (1.3, 0)
  line L6 (0.5, 12.2) -> (0.5, 0)
  line L7 (1.3, 12.2) -> (0.5, 12.2)
  line L8 (1.3, 0) -> (1.3, 12.2)
  line L9 (30.5, 0) -> (31.3, 0)
  line L10 (30.5, 12.2) -> (30.5, 0)
  line L11 (31.3, 12.2) -> (30.5, 12.2)
  line L12 (31.3, 0) -> (31.3, 12.2)
  point P3 (0.5, 12.2)
  point P8 (0.5, 12.2)
  point P6 (1.3, 0)
  point P12 (30.5, 12.2)
  point P5 (31.3, 0)
  point P10 (31.3, 0)
  point P13 (31.3, 12.2)
  point P9 (1.3, 12.2)
  horizontal L5
  vertical L6
  horizontal L7
  vertical L8
  coincident P3 P8
  coincident L3 P6
  horizontal L9
  vertical L10
  horizontal L11
  vertical L12
  coincident L1 P12
  coincident P5 P10
  dimension "d45_2" distance P12 P13 = 0.8
  dimension "d46_2" distance P8 P9 = 0.8
extrude "Extrude9" add sketch "Sketch8" along normal blind 13 named "d47_3"
fillet "Fillet2" radius 4 named "d49_3"
chamfer "Chamfer1" distance 3 named "d50_3"
fillet "Fillet3" radius 2 named "d51_3"
fillet "Fillet4" radius 2 named "d52_3"
sketch "Sketch1" plane through (0, 0, 0) normal (0, 0, 1) x axis (1, 0, 0)
  line L1 (31.8, 0) -> (0, 0)
  line L2 (31.8, 80) -> (31.8, 0)
  line L3 (0, 80) -> (31.8, 80)
  line L4 (0, 0) -> (0, 80)
  point P1 (0, 0)
  point P2 (0, 0)
  point P3 (31.8, 0)
  point P4 (31.8, 80)
  horizontal L1
  vertical L2
  horizontal L3
  vertical L4
  coincident P1 P2
  dimension "d1_4" distance P2 P3 = 31.8
  dimension "d2_4" distance P3 P4 = 80
extrude "Extrude1" new body sketch "Sketch1" along normal blind 26.2 named "d3_4"
shell "Shell1" innerThickness 0.8 named "d5_4"
work_plane "WorkPlane1" AlongDistance -18.4 named "d6_4"
sketch "Sketch3" plane through (0, 80, 0) normal (0, 1, 0) x axis (-1, 0, 0)
  line L1 (0, 0) -> (-31.8, 0)
  line L2 (0, 26.2) -> (0, 0)
  line L3 (-31.8, 26.2) -> (0, 26.2)
  line L4 (-31.8, 0) -> (-31.8, 26.2)
  line L5 (-15.9, 0) -> (-15.9, 26.2)
  line L6 (-27.55, 28.45) -> (-27.55, 27.45)
  line L7 (-23.3, 29.7) -> (-26.3, 29.7)
  line L8 (-22.05, 27.45) -> (-22.05, 28.45)
  line L9 (-20.8, 26.2) -> (-28.8, 26.2)
  line L10 (-8.5, 29.7) -> (-5.5, 29.7)
  line L11 (-4.25, 28.45) -> (-4.25, 27.45)
  line L12 (-11, 26.2) -> (-3, 26.2)
  line L13 (-9.75, 27.45) -> (-9.75, 28.45)
  arc A1 centre (-28.8, 27.45) radius 1.25 clockwise from (-27.55, 27.45) to (-28.8, 26.2)
  arc A2 centre (-26.3, 28.45) radius 1.25 clockwise from (-27.55, 28.45) to (-26.3, 29.7)
  arc A3 centre (-23.3, 28.45) radius 1.25 clockwise from (-23.3, 29.7) to (-22.05, 28.45)
  arc A4 centre (-20.8, 27.45) radius 1.25 clockwise from (-20.8, 26.2) to (-22.05, 27.45)
  arc A5 centre (-5.5, 28.45) radius 1.25 clockwise from (-5.5, 29.7) to (-4.25, 28.45)
  arc A6 centre (-11, 27.45) radius 1.25 clockwise from (-9.75, 27.45) to (-11, 26.2)
  arc A7 centre (-3, 27.45) radius 1.25 clockwise from (-3, 26.2) to (-4.25, 27.45)
  arc A8 centre (-8.5, 28.45) radius 1.25 clockwise from (-9.75, 28.45) to (-8.5, 29.7)
  point P10 (-15.9, 26.2)
  point P11 (-15.9, 0)
  point P20 (-24.8, 29.7)
  point P12 (-27.55, 27.45)
  point P27 (-4.25, 27.45)
  point P13 (-27.55, 28.45)
  point P21 (-4.25, 28.45)
  point P14 (-26.3, 29.7)
  point P28 (-5.5, 29.7)
  point P15 (-23.3, 29.7)
  point P26 (-8.5, 29.7)
  point P16 (-22.05, 28.45)
  point P23 (-9.75, 28.45)
  point P17 (-22.05, 27.45)
  point P22 (-9.75, 27.45)
  point P18 (-28.8, 26.2)
  point P30 (-3, 26.2)
  point P19 (-20.8, 26.2)
  point P29 (-11, 26.2)
  point P31 (-7, 29.7)
  midpoint L3 P10
  perpendicular L3 L5
  coincident L1 P11
  horizontal L7
  tangent L7 A2
  tangent L6 A2
  tangent L6 A1
  tangent L7 A3
  tangent L8 A3
  tangent L8 A4
  tangent L9 A4
  tangent L9 A1
  equal A1 A2
  equal A2 A3
  equal A3 A4
  collinear L3 L9
  vertical L8
  vertical L6
  midpoint L7 P20
  symmetric L5 P12 P27
  symmetric L5 P13 P21
  symmetric L5 P14 P28
  symmetric L5 P15 P26
  symmetric L5 P16 P23
  symmetric L5 P17 P22
  symmetric L5 P18 P30
  symmetric L5 P19 P29
  symmetric L5 P20 P31
  symmetric L5 A1 A7
  symmetric L5 A2 A5
  symmetric L5 A3 A8
  symmetric L5 A4 A6
  dimension "d18_3" distance L4 P20 = 7
  dimension "d19_4" distance L7 L9 = 3.5
  dimension "d20_3" distance L6 L8 = 5.5
  dimension "d21_4" radius A1 = 1.25
extrude "Extrude3" add sketch "Sketch3" profile of L3 A1 A2 A3 A4 L6 L7 L8 L9 A5 L10 A6 A7 L11 L12 A8 L13 against normal blind 0.8 named "d22_4"
sketch "Sketch4" plane through (31.8, 0, 0) normal (1, 0, 0) x axis (0, 1, 0)
  line L1 (80, 0) -> (0, 0)
  line L2 (80, 26.2) -> (80, 0)
  line L3 (0, 26.2) -> (80, 26.2)
  line L4 (0, 0) -> (0, 26.2)
  line L5 (10.1071, 17) -> (0.9071, 26.2)
  line L6 (7.8528, 26.2) -> (0.9071, 26.2)
  line L7 (69.7311, 17) -> (10.1071, 17)
  line L8 (78.9311, 26.2) -> (69.7311, 17)
  line L9 (0.9071, 26.2) -> (78.9311, 26.2)
  point P6 (0.9071, 26.2)
  point P10 (78.9311, 26.2)
  horizontal L6
  coincident L3 P6
  horizontal L7
  coincident L3 P10
  dimension "d24_4" angle L5 L6 = 45
  dimension "d25_4" angle L7 L8 = 135
  dimension "d26_4" distance L1 L7 = 17
extrude "Extrude4" cut sketch "Sketch4" profile of L3 L5 L7 L8 L9 against normal blind 31.8 named "d27_4"
extrude "Extrude5" add of existing geometry blind 0.4 named "d29_4"
sketch "Sketch5" plane through (0, 0, 0) normal (0, -1, 0) x axis (1, 0, 0)
  line L1 (31.8, 0) -> (0, 0)
  line L2 (31.8, 26.2) -> (31.8, 0)
  line L3 (0, 26.2) -> (31.8, 26.2)
  line L4 (0, 0) -> (0, 26.2)
  line L5 (31.3, 13.8) -> (0.5, 13.8)
  line L6 (31.3, 13) -> (31.3, 13.8)
  line L7 (0.5, 13) -> (31.3, 13)
  line L8 (0.5, 13.8) -> (0.5, 13)
  horizontal L5
  vertical L6
  horizontal L7
  vertical L8
  dimension "d31_4" distance L4 L8 = 0.5
  dimension "d32_4" distance L2 L6 = 0.5
  dimension "d33_4" distance L5 L7 = 0.8
  dimension "d34_4" distance L1 L7 = 13
extrude "Extrude6" add sketch "Sketch5" profile of L5 L6 L7 L8 along normal blind 13 named "d35_4"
